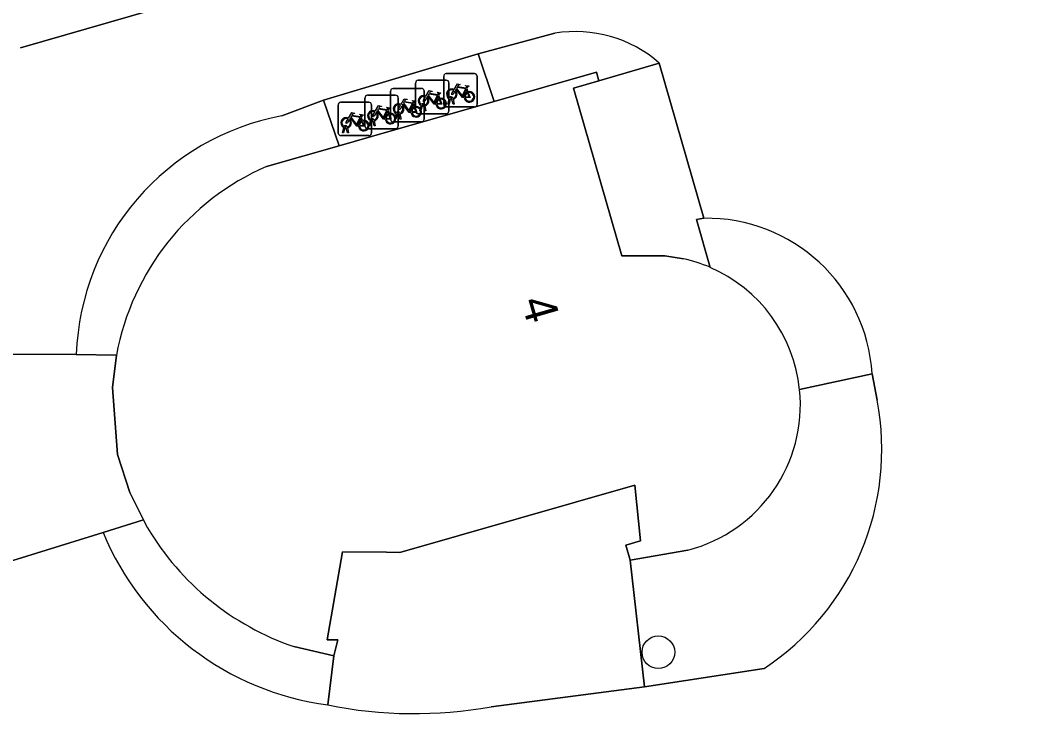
# Model space of a CAD drawing. Extents: x 162156 to 163172, y 378995 to 380779.
# Drawn here: x 162489.04 to 162519.6, y 379970.33 to 379991.07 of the extents above; entities that cross this region are included whole.
import ezdxf

# ---------------------------------------------------------------- set-up
doc = ezdxf.new("R2010")
doc.units = 0
for name, color, linetype in [('IMGEO_Boom', 7, 'Continuous'), ('IMGEO_Fietsenrek', 7, 'Continuous'), ('IMGEO_Groenvoorziening', 7, 'Continuous'), ('IMGEO_Haag', 7, 'Continuous'), ('IMGEO_Pand', 7, 'Continuous'), ('IMGEO_Pand_nummerreeks', 7, 'Continuous'), ('IMGEO_Parkeervlak_open', 7, 'Continuous'), ('IMGEO_Voetpad_open', 7, 'Continuous')]:
    doc.layers.add(name, color=color, linetype=linetype)

msp = doc.modelspace()

# ---------------------------------------------------------------- linework, layer by layer
at = {"layer": 'IMGEO_Boom'}
msp.add_circle((162508.129, 379972.166), 0.489, dxfattribs=at)
at = {"layer": 'IMGEO_Fietsenrek'}
for p, q in [((162501.783, 379989.484), (162502.624, 379989.484)), ((162502.624, 379989.484), (162501.783, 379989.484)), ((162500.864, 379988.358), (162500.864, 379989.199)), ((162500.864, 379989.199), (162500.864, 379988.358)), ((162500.939, 379989.283), (162501.78, 379989.283)), ((162501.78, 379989.283), (162500.939, 379989.283)), ((162501.708, 379988.559), (162501.708, 379989.4)), ((162501.708, 379989.4), (162501.708, 379988.559)), ((162501.864, 379989.208), (162501.864, 379988.367)), ((162501.864, 379988.367), (162501.864, 379989.208)), ((162502.708, 379989.409), (162502.708, 379988.568)), ((162502.708, 379988.568), (162502.708, 379989.409)), ((162500.118, 379988.113), (162500.118, 379988.954)), ((162500.118, 379988.954), (162500.118, 379988.113)), ((162500.193, 379989.038), (162501.034, 379989.038)), ((162501.034, 379989.038), (162500.193, 379989.038)), ((162501.118, 379988.963), (162501.118, 379988.122)), ((162501.118, 379988.122), (162501.118, 379988.963)), ((162502.395, 379989.033), (162502.431, 379988.938)), ((162498.548, 379987.7), (162498.548, 379988.541)), ((162498.548, 379988.541), (162498.548, 379987.7)), ((162498.623, 379988.625), (162499.464, 379988.625)), ((162499.464, 379988.625), (162498.623, 379988.625)), ((162499.348, 379987.909), (162499.348, 379988.75)), ((162499.348, 379988.75), (162499.348, 379987.909)), ((162499.423, 379988.834), (162500.264, 379988.834)), ((162500.264, 379988.834), (162499.423, 379988.834)), ((162499.548, 379988.55), (162499.548, 379987.709)), ((162499.548, 379987.709), (162499.548, 379988.55)), ((162500.348, 379988.759), (162500.348, 379987.918)), ((162500.348, 379987.918), (162500.348, 379988.759)), ((162500.805, 379988.587), (162500.841, 379988.492)), ((162501.102, 379988.539), (162501.101, 379988.543)), ((162501.133, 379988.55), (162501.134, 379988.543)), ((162501.551, 379988.832), (162501.587, 379988.737)), ((162501.835, 379988.568), (162501.874, 379988.728)), ((162501.869, 379988.568), (162501.835, 379988.568)), ((162501.904, 379988.716), (162501.869, 379988.568)), ((162501.946, 379988.74), (162501.945, 379988.744)), ((162501.987, 379988.568), (162501.953, 379988.71)), ((162501.977, 379988.751), (162501.978, 379988.744)), ((162501.985, 379988.714), (162502.02, 379988.568)), ((162502.02, 379988.568), (162501.987, 379988.568)), ((162500.035, 379988.383), (162500.071, 379988.288)), ((162500.245, 379988.122), (162500.284, 379988.282)), ((162500.314, 379988.27), (162500.279, 379988.122)), ((162500.356, 379988.294), (162500.355, 379988.298)), ((162500.397, 379988.122), (162500.363, 379988.264)), ((162500.387, 379988.305), (162500.388, 379988.298)), ((162500.395, 379988.268), (162500.43, 379988.122)), ((162501.789, 379988.283), (162500.948, 379988.283)), ((162500.948, 379988.283), (162501.789, 379988.283)), ((162500.991, 379988.367), (162501.03, 379988.527)), ((162501.025, 379988.367), (162500.991, 379988.367)), ((162501.06, 379988.515), (162501.025, 379988.367)), ((162501.143, 379988.367), (162501.109, 379988.509)), ((162501.141, 379988.513), (162501.176, 379988.367)), ((162501.176, 379988.367), (162501.143, 379988.367)), ((162502.633, 379988.484), (162501.792, 379988.484)), ((162501.792, 379988.484), (162502.633, 379988.484)), ((162499.235, 379988.174), (162499.271, 379988.079)), ((162499.475, 379987.918), (162499.514, 379988.078)), ((162499.544, 379988.066), (162499.509, 379987.918)), ((162499.586, 379988.09), (162499.585, 379988.094)), ((162499.627, 379987.918), (162499.593, 379988.06)), ((162499.617, 379988.101), (162499.618, 379988.094)), ((162499.625, 379988.064), (162499.66, 379987.918)), ((162501.043, 379988.038), (162500.202, 379988.038)), ((162500.202, 379988.038), (162501.043, 379988.038)), ((162500.279, 379988.122), (162500.245, 379988.122)), ((162500.43, 379988.122), (162500.397, 379988.122)), ((162499.473, 379987.625), (162498.632, 379987.625)), ((162498.632, 379987.625), (162499.473, 379987.625)), ((162498.675, 379987.709), (162498.714, 379987.869)), ((162498.709, 379987.709), (162498.675, 379987.709)), ((162498.744, 379987.857), (162498.709, 379987.709)), ((162498.786, 379987.881), (162498.785, 379987.885)), ((162498.827, 379987.709), (162498.793, 379987.851)), ((162498.817, 379987.892), (162498.818, 379987.885)), ((162498.825, 379987.855), (162498.86, 379987.709)), ((162498.86, 379987.709), (162498.827, 379987.709)), ((162500.273, 379987.834), (162499.432, 379987.834)), ((162499.432, 379987.834), (162500.273, 379987.834)), ((162499.509, 379987.918), (162499.475, 379987.918)), ((162499.66, 379987.918), (162499.627, 379987.918))]:
    msp.add_line(p, q, dxfattribs=at)
for points in [[(162502.021, 379989.01), (162502.116, 379989.174), (162502.202, 379989.16), (162502.204, 379989.151), (162502.148, 379989.14), (162502.121, 379989.095), (162502.377, 379989.054)], [(162501.177, 379988.809), (162501.272, 379988.973), (162501.358, 379988.959), (162501.36, 379988.95), (162501.304, 379988.939), (162501.277, 379988.894), (162501.533, 379988.853)], [(162501.52, 379988.828), (162501.263, 379988.869), (162501.246, 379988.84), (162501.413, 379988.62), (162501.52, 379988.828)], [(162501.533, 379988.853), (162501.558, 379988.902), (162501.552, 379988.906), (162501.529, 379988.91), (162501.517, 379988.917), (162501.516, 379988.92), (162501.518, 379988.925), (162501.613, 379988.91), (162501.615, 379988.9), (162501.605, 379988.887), (162501.593, 379988.881), (162501.579, 379988.887), (162501.551, 379988.832)], [(162502.042, 379988.958), (162501.99, 379988.868), (162501.95, 379988.843), (162501.951, 379988.89), (162502.006, 379988.984)], [(162502.317, 379988.766), (162502.267, 379988.766), (162502.076, 379989.017), (162502.057, 379988.985)], [(162502.364, 379989.029), (162502.107, 379989.07), (162502.09, 379989.041), (162502.257, 379988.821), (162502.364, 379989.029)], [(162502.412, 379988.931), (162502.382, 379989.008), (162502.273, 379988.79), (162502.316, 379988.79)], [(162502.346, 379988.79), (162502.466, 379988.789), (162502.422, 379988.903)], [(162502.442, 379988.91), (162502.497, 379988.765), (162502.347, 379988.765)], [(162502.377, 379989.054), (162502.402, 379989.103), (162502.396, 379989.107), (162502.373, 379989.111), (162502.361, 379989.118), (162502.36, 379989.121), (162502.362, 379989.126), (162502.457, 379989.111), (162502.459, 379989.101), (162502.449, 379989.088), (162502.437, 379989.082), (162502.423, 379989.088), (162502.395, 379989.033)], [(162500.452, 379988.512), (162500.4, 379988.422), (162500.36, 379988.397), (162500.361, 379988.444), (162500.416, 379988.538)], [(162500.431, 379988.564), (162500.526, 379988.728), (162500.612, 379988.714), (162500.614, 379988.705), (162500.558, 379988.694), (162500.531, 379988.649), (162500.787, 379988.608)], [(162500.727, 379988.32), (162500.677, 379988.32), (162500.486, 379988.571), (162500.467, 379988.539)], [(162500.774, 379988.583), (162500.517, 379988.624), (162500.5, 379988.595), (162500.667, 379988.375), (162500.774, 379988.583)], [(162500.822, 379988.485), (162500.792, 379988.562), (162500.683, 379988.344), (162500.726, 379988.344)], [(162500.787, 379988.608), (162500.812, 379988.657), (162500.806, 379988.661), (162500.783, 379988.665), (162500.771, 379988.672), (162500.77, 379988.675), (162500.772, 379988.68), (162500.867, 379988.665), (162500.869, 379988.655), (162500.859, 379988.642), (162500.847, 379988.636), (162500.833, 379988.642), (162500.805, 379988.587)], [(162501.198, 379988.757), (162501.146, 379988.667), (162501.106, 379988.642), (162501.107, 379988.689), (162501.162, 379988.783)], [(162501.473, 379988.565), (162501.423, 379988.565), (162501.232, 379988.816), (162501.213, 379988.784)], [(162501.568, 379988.73), (162501.538, 379988.807), (162501.429, 379988.589), (162501.472, 379988.589)], [(162501.502, 379988.589), (162501.622, 379988.588), (162501.578, 379988.702)], [(162501.598, 379988.709), (162501.653, 379988.564), (162501.503, 379988.564)], [(162498.861, 379988.151), (162498.956, 379988.315), (162499.042, 379988.301), (162499.044, 379988.292), (162498.988, 379988.281), (162498.961, 379988.236), (162499.217, 379988.195)], [(162499.217, 379988.195), (162499.242, 379988.244), (162499.236, 379988.248), (162499.213, 379988.252), (162499.201, 379988.259), (162499.2, 379988.262), (162499.202, 379988.267), (162499.297, 379988.252), (162499.299, 379988.242), (162499.289, 379988.229), (162499.277, 379988.223), (162499.263, 379988.229), (162499.235, 379988.174)], [(162499.682, 379988.308), (162499.63, 379988.218), (162499.59, 379988.193), (162499.591, 379988.24), (162499.646, 379988.334)], [(162499.661, 379988.36), (162499.756, 379988.524), (162499.842, 379988.51), (162499.844, 379988.501), (162499.788, 379988.49), (162499.761, 379988.445), (162500.017, 379988.404)], [(162499.957, 379988.116), (162499.907, 379988.116), (162499.716, 379988.367), (162499.697, 379988.335)], [(162500.004, 379988.379), (162499.747, 379988.42), (162499.73, 379988.391), (162499.897, 379988.171), (162500.004, 379988.379)], [(162500.052, 379988.281), (162500.022, 379988.358), (162499.913, 379988.14), (162499.956, 379988.14)], [(162499.986, 379988.14), (162500.106, 379988.139), (162500.062, 379988.253)], [(162500.082, 379988.26), (162500.137, 379988.115), (162499.987, 379988.115)], [(162500.017, 379988.404), (162500.042, 379988.453), (162500.036, 379988.457), (162500.013, 379988.461), (162500.001, 379988.468), (162500, 379988.471), (162500.002, 379988.476), (162500.097, 379988.461), (162500.099, 379988.451), (162500.089, 379988.438), (162500.077, 379988.432), (162500.063, 379988.438), (162500.035, 379988.383)], [(162500.756, 379988.344), (162500.876, 379988.343), (162500.832, 379988.457)], [(162500.852, 379988.464), (162500.907, 379988.319), (162500.757, 379988.319)], [(162498.882, 379988.099), (162498.83, 379988.009), (162498.79, 379987.984), (162498.791, 379988.031), (162498.846, 379988.125)], [(162499.157, 379987.907), (162499.107, 379987.907), (162498.916, 379988.158), (162498.897, 379988.126)], [(162499.204, 379988.17), (162498.947, 379988.211), (162498.93, 379988.182), (162499.097, 379987.962), (162499.204, 379988.17)], [(162499.252, 379988.072), (162499.222, 379988.149), (162499.113, 379987.931), (162499.156, 379987.931)], [(162499.186, 379987.931), (162499.306, 379987.93), (162499.262, 379988.044)], [(162499.282, 379988.051), (162499.337, 379987.906), (162499.187, 379987.906)]]:
    msp.add_lwpolyline(points, dxfattribs=at)
for centre, radius, start, end in [((162501.786, 379989.406), 0.0779, 92.4484, 184.2845), ((162501.786, 379989.406), 0.0779, 92.4484, 184.2845), ((162502.63, 379989.406), 0.0779, 2.4484, 94.2845), ((162502.63, 379989.406), 0.0779, 2.4484, 94.2845), ((162500.942, 379989.205), 0.0779, 92.4484, 184.2845), ((162500.942, 379989.205), 0.0779, 92.4484, 184.2845), ((162501.786, 379989.205), 0.0779, 2.4484, 94.2845), ((162501.786, 379989.205), 0.0779, 2.4484, 94.2845), ((162500.196, 379988.96), 0.0779, 92.4484, 184.2845), ((162500.196, 379988.96), 0.0779, 92.4484, 184.2845), ((162501.04, 379988.96), 0.0779, 2.4484, 94.2845), ((162501.04, 379988.96), 0.0779, 2.4484, 94.2845), ((162501.948, 379988.869), 0.159, 62.6766, 242.1369), ((162501.948, 379988.869), 0.129, 63.3192, 238.903), ((162501.948, 379988.869), 0.129, 283.6043, 43.4302), ((162501.948, 379988.869), 0.159, 283.5766, 46.6042), ((162502.475, 379988.785), 0.159, 113.3408, 178.3217), ((162502.475, 379988.785), 0.159, 187.0065, 105.7708), ((162502.475, 379988.785), 0.129, 113.923, 177.9556), ((162502.475, 379988.785), 0.129, 188.6715, 104.5883), ((162498.626, 379988.547), 0.0779, 92.4484, 184.2845), ((162498.626, 379988.547), 0.0779, 92.4484, 184.2845), ((162499.426, 379988.756), 0.0779, 92.4484, 184.2845), ((162499.426, 379988.756), 0.0779, 92.4484, 184.2845), ((162499.47, 379988.547), 0.0779, 2.4484, 94.2845), ((162499.47, 379988.547), 0.0779, 2.4484, 94.2845), ((162500.358, 379988.423), 0.159, 62.6766, 242.1369), ((162500.358, 379988.423), 0.129, 63.3192, 238.903), ((162500.27, 379988.756), 0.0779, 2.4484, 94.2845), ((162500.27, 379988.756), 0.0779, 2.4484, 94.2845), ((162500.358, 379988.423), 0.159, 283.5766, 46.6042), ((162501.104, 379988.668), 0.159, 62.6766, 242.1369), ((162501.104, 379988.668), 0.129, 63.3192, 238.903), ((162501.084, 379988.539), 0.0499, 12.8025, 158.6934), ((162501.084, 379988.539), 0.0174, 12.8025, 163.4502), ((162501.104, 379988.668), 0.129, 253.415, 269.0204), ((162501.104, 379988.668), 0.129, 283.6043, 43.4302), ((162501.104, 379988.668), 0.159, 283.5766, 46.6042), ((162501.631, 379988.584), 0.159, 113.3408, 178.3217), ((162501.631, 379988.584), 0.159, 187.0065, 105.7708), ((162501.631, 379988.584), 0.129, 113.923, 177.9556), ((162501.631, 379988.584), 0.129, 188.6715, 104.5883), ((162501.786, 379988.562), 0.0779, 182.4484, 274.2845), ((162501.786, 379988.562), 0.0779, 182.4484, 274.2845), ((162501.928, 379988.74), 0.0499, 12.8025, 158.6934), ((162501.948, 379988.869), 0.159, 253.9967, 271.7867), ((162501.928, 379988.74), 0.0174, 12.8025, 163.4502), ((162501.948, 379988.869), 0.129, 253.415, 269.0204), ((162502.63, 379988.562), 0.0779, 272.4484, 4.2845), ((162502.63, 379988.562), 0.0779, 272.4484, 4.2845), ((162499.588, 379988.219), 0.159, 62.6766, 242.1369), ((162499.588, 379988.219), 0.129, 63.3192, 238.903), ((162499.588, 379988.219), 0.129, 283.6043, 43.4302), ((162499.588, 379988.219), 0.159, 283.5766, 46.6042), ((162500.115, 379988.135), 0.159, 113.3408, 178.3217), ((162500.115, 379988.135), 0.159, 187.0065, 105.7708), ((162500.115, 379988.135), 0.129, 113.923, 177.9556), ((162500.115, 379988.135), 0.129, 188.6715, 104.5883), ((162500.338, 379988.294), 0.0499, 12.8025, 158.6934), ((162500.358, 379988.423), 0.159, 253.9967, 271.7867), ((162500.338, 379988.294), 0.0174, 12.8025, 163.4502), ((162500.358, 379988.423), 0.129, 253.415, 269.0204), ((162500.358, 379988.423), 0.129, 283.6043, 43.4302), ((162500.885, 379988.339), 0.159, 113.3408, 178.3217), ((162500.885, 379988.339), 0.159, 187.0065, 105.7708), ((162500.885, 379988.339), 0.129, 113.923, 177.9556), ((162500.885, 379988.339), 0.129, 188.6715, 104.5883), ((162500.942, 379988.361), 0.0779, 182.4484, 274.2845), ((162500.942, 379988.361), 0.0779, 182.4484, 274.2845), ((162501.104, 379988.668), 0.159, 253.9967, 271.7867), ((162501.786, 379988.361), 0.0779, 272.4484, 4.2845), ((162501.786, 379988.361), 0.0779, 272.4484, 4.2845), ((162498.788, 379988.01), 0.159, 62.6766, 242.1369), ((162498.788, 379988.01), 0.129, 63.3192, 238.903), ((162498.768, 379987.881), 0.0499, 12.8025, 158.6934), ((162498.788, 379988.01), 0.129, 283.6043, 43.4302), ((162498.788, 379988.01), 0.159, 283.5766, 46.6042), ((162499.315, 379987.926), 0.159, 113.3408, 178.3217), ((162499.315, 379987.926), 0.159, 187.0065, 105.7708), ((162499.315, 379987.926), 0.129, 113.923, 177.9556), ((162499.315, 379987.926), 0.129, 188.6715, 104.5883), ((162499.568, 379988.09), 0.0499, 12.8025, 158.6934), ((162499.588, 379988.219), 0.159, 253.9967, 271.7867), ((162499.568, 379988.09), 0.0174, 12.8025, 163.4502), ((162499.588, 379988.219), 0.129, 253.415, 269.0204), ((162500.196, 379988.116), 0.0779, 182.4484, 274.2845), ((162500.196, 379988.116), 0.0779, 182.4484, 274.2845), ((162501.04, 379988.116), 0.0779, 272.4484, 4.2845), ((162501.04, 379988.116), 0.0779, 272.4484, 4.2845), ((162498.626, 379987.703), 0.0779, 182.4484, 274.2845), ((162498.626, 379987.703), 0.0779, 182.4484, 274.2845), ((162498.788, 379988.01), 0.159, 253.9967, 271.7867), ((162498.768, 379987.881), 0.0174, 12.8025, 163.4502), ((162498.788, 379988.01), 0.129, 253.415, 269.0204), ((162499.426, 379987.912), 0.0779, 182.4484, 274.2845), ((162499.426, 379987.912), 0.0779, 182.4484, 274.2845), ((162499.47, 379987.703), 0.0779, 272.4484, 4.2845), ((162499.47, 379987.703), 0.0779, 272.4484, 4.2845), ((162500.27, 379987.912), 0.0779, 272.4484, 4.2845), ((162500.27, 379987.912), 0.0779, 272.4484, 4.2845)]:
    msp.add_arc(centre, radius, start, end, dxfattribs=at)
at = {"layer": 'IMGEO_Groenvoorziening'}
for points in [[(162489.042, 379990.254), (162512.527, 379997.031)], [(162505.035, 379990.689), (162502.74, 379990.077)], [(162502.74, 379990.077), (162503.217, 379988.648), (162506.275, 379989.522), (162506.35, 379989.262), (162508.155, 379989.798)], [(162496.405, 379986.702), (162498.576, 379987.322), (162498.109, 379988.686), (162496.868, 379988.217)], [(162509.487, 379985.152), (162509.275, 379985.113), (162509.675, 379983.684)], [(162490.714, 379981.076), (162491.914, 379981.055)], [(162514.524, 379980.502), (162512.356, 379980.024)], [(162512.356, 379980.024), (162514.524, 379980.502)], [(162514.675, 379979.706), (162514.524, 379980.502)], [(162492.848, 379975.888), (162492.728, 379976.129), (162491.513, 379975.749)], [(162509.015, 379975.222), (162507.286, 379974.922), (162507.711, 379971.131), (162511.292, 379971.682)], [(162498.238, 379970.588), (162498.418, 379972.056), (162497.219, 379972.337)]]:
    msp.add_lwpolyline(points, dxfattribs=at)
for centre, radius, start, end in [((162505.657, 379986.959), 3.781, 48.6556, 99.4682), ((162498.24, 379980.813), 7.53, 100.496, 177.9955), ((162499.474, 379979.652), 7.689, 113.5231, 169.4871), ((162509.58, 379980.199), 4.953, 3.5018, 91.0737), ((162507.895, 379979.568), 4.484, 5.8309, 66.6157), ((162507.891, 379979.567), 4.488, 284.5013, 5.842), ((162506.967, 379978.231), 7.848, 303.4432, 10.8353), ((162499.347, 379978.995), 8.479, 202.5049, 262.4873), ((162499.856, 379980.049), 8.15, 210.6975, 251.1217)]:
    msp.add_arc(centre, radius, start, end, dxfattribs=at)
at = {"layer": 'IMGEO_Haag'}
for points in [[(162509.487, 379985.152), (162509.275, 379985.113), (162509.675, 379983.684)], [(162512.356, 379980.024), (162514.524, 379980.502)]]:
    msp.add_lwpolyline(points, dxfattribs=at)
for centre, radius, start, end in [((162509.58, 379980.199), 4.953, 3.5018, 91.0737), ((162507.895, 379979.568), 4.484, 5.8309, 66.6157)]:
    msp.add_arc(centre, radius, start, end, dxfattribs=at)
at = {"layer": 'IMGEO_Pand'}
for points in [[(162508.885, 379983.942), (162508.319, 379984.028), (162507.038, 379984.028), (162505.591, 379989.043), (162506.35, 379989.262), (162506.275, 379989.522), (162503.217, 379988.648), (162500, 379987.729), (162498.576, 379987.322), (162496.405, 379986.702)], [(162491.914, 379981.055), (162491.797, 379980.085), (162491.948, 379978.081), (162492.319, 379976.948), (162492.728, 379976.129), (162492.848, 379975.888)], [(162497.219, 379972.337), (162498.418, 379972.056), (162498.538, 379972.536), (162498.218, 379972.536), (162498.68, 379975.175), (162500, 379975.16), (162500.397, 379975.155), (162507.421, 379977.162), (162507.599, 379975.498), (162507.158, 379975.372), (162507.286, 379974.922), (162509.015, 379975.222)]]:
    msp.add_lwpolyline(points, dxfattribs=at)
for centre, radius, start, end in [((162499.474, 379979.652), 7.689, 113.5231, 169.4871), ((162507.87, 379979.497), 4.56, 66.6852, 77.1425), ((162507.895, 379979.568), 4.484, 5.8309, 66.6157), ((162507.891, 379979.567), 4.488, 284.5013, 5.842), ((162499.856, 379980.049), 8.15, 210.6975, 251.1217)]:
    msp.add_arc(centre, radius, start, end, dxfattribs=at)
at = {"layer": 'IMGEO_Parkeervlak_open'}
for points in [[(162507.286, 379974.922), (162507.158, 379975.372), (162507.599, 379975.498), (162507.421, 379977.162), (162500.397, 379975.155), (162500, 379975.16), (162498.68, 379975.175), (162498.218, 379972.536), (162498.538, 379972.536), (162498.418, 379972.056), (162498.238, 379970.588)], [(162503.124, 379970.536), (162507.711, 379971.131), (162507.286, 379974.922)]]:
    msp.add_lwpolyline(points, dxfattribs=at)
msp.add_arc((162500.817, 379983.367), 13.037, 258.5892, 280.1913, dxfattribs=at)
at = {"layer": 'IMGEO_Voetpad_open'}
for points in [[(162556.483, 380004.641), (162566.165, 380006.855), (162566.652, 380006.967), (162566.273, 380008.252), (162564.682, 380007.818), (162564.55, 380008.3), (162563.36, 380012.277), (162563.329, 380012.388), (162557.25, 380010.193), (162556.197, 380009.943), (162547.53, 380007.164), (162514.588, 379997.596), (162512.527, 379997.031), (162489.042, 379990.254)], [(162496.868, 379988.217), (162498.109, 379988.686), (162502.74, 379990.077), (162505.035, 379990.689)], [(162508.155, 379989.798), (162506.35, 379989.262), (162505.591, 379989.043), (162507.038, 379984.028), (162508.319, 379984.028), (162508.885, 379983.942)], [(162509.675, 379983.684), (162509.275, 379985.113), (162509.487, 379985.152), (162508.155, 379989.798)], [(162508.155, 379989.798), (162509.487, 379985.152)], [(162491.513, 379975.749), (162487.52, 379974.511), (162486.653, 379981.085), (162490.714, 379981.076)], [(162514.524, 379980.502), (162514.675, 379979.706)], [(162511.292, 379971.682), (162507.711, 379971.131), (162503.124, 379970.536)]]:
    msp.add_lwpolyline(points, dxfattribs=at)
for points in [[(162502.74, 379990.077), (162498.109, 379988.686), (162498.576, 379987.322), (162500, 379987.729), (162503.217, 379988.648)], [(162491.797, 379980.085), (162491.914, 379981.055), (162490.714, 379981.076), (162486.653, 379981.085), (162487.52, 379974.511), (162491.513, 379975.749), (162492.728, 379976.129), (162492.319, 379976.948), (162491.948, 379978.081)]]:
    msp.add_lwpolyline(points, close=True, dxfattribs=at)
for centre, radius, start, end in [((162505.657, 379986.959), 3.781, 48.6556, 99.4682), ((162498.24, 379980.813), 7.53, 100.496, 177.9955), ((162509.58, 379980.199), 4.953, 3.5018, 91.0737), ((162507.87, 379979.497), 4.56, 66.6852, 77.1425), ((162506.967, 379978.231), 7.848, 303.4432, 10.8353), ((162499.347, 379978.995), 8.479, 202.5049, 262.4873), ((162500.817, 379983.367), 13.037, 258.5892, 280.1913)]:
    msp.add_arc(centre, radius, start, end, dxfattribs=at)

# ---------------------------------------------------------------- texts
at = {"layer": 'IMGEO_Pand_nummerreeks'}
msp.add_text('4', height=1, rotation=286.0942, dxfattribs=at).set_placement((162504.017, 379982.668))

doc.saveas('drawing.dxf')
